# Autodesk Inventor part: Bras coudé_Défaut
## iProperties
Shininess: 64.0
Length Units: 11269
Angle Units: 11279
Time Units: 11290
Mass Units: 11283
Length Display Precision: 3
Angle Display Precision: 2
Compacted: True
Part Number: Bras coudé_Défaut
Document SubType Name: Modeling
Created: 2006-11
Material: Par défaut
Designer: profs_sti
Density: 0.0
Volumn: 0.0
Area: 0.0
PropertySet Name: Model Information
Control State: 0
Master: False
Checked Out: False
Author: profs_sti
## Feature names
1. Base1
